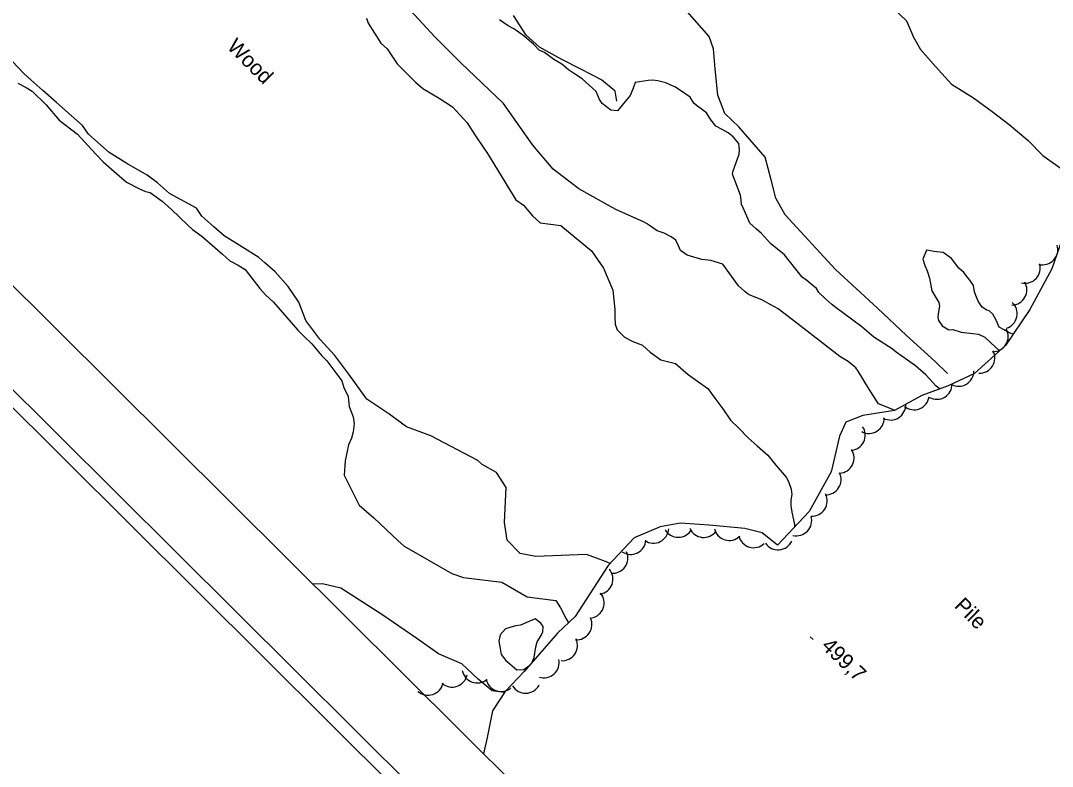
# Model space of a CAD drawing. Extents: x 642515 to 647219, y 6080136 to 6084356.
# Drawn here: x 643071.4 to 643274.3, y 6081637.9 to 6081784.5 of the extents above; entities that cross this region are included whole.
import ezdxf

# ---------------------------------------------------------------- set-up
doc = ezdxf.new("R2010")
doc.units = 0
for name, color, linetype in [('Level 1', 7, 'Continuous'), ('Level 2', 7, 'Continuous'), ('Level 3', 7, 'Continuous'), ('Level 4', 7, 'Continuous'), ('Level 44', 7, 'Continuous'), ('Level 57', 7, 'Continuous'), ('Level 60', 7, 'Continuous')]:
    doc.layers.add(name, color=color, linetype=linetype)

msp = doc.modelspace()

# ---------------------------------------------------------------- linework, layer by layer
at = {"layer": 'Level 1'}
msp.add_lwpolyline([(643187.32, 6081677.78), (643186.4, 6081678.13), (643184.6, 6081678.82), (643182.64, 6081679.51), (643172.67, 6081679.14), (643169.6, 6081679.75), (643167.04, 6081682.32), (643166.51, 6081685.81), (643166.88, 6081692.72), (643164.94, 6081695.65), (643162.12, 6081697.24), (643161.28, 6081697.99), (643152.02, 6081702.87), (643147.28, 6081704.66), (643143.77, 6081707.17), (643139.43, 6081710.11), (643135.93, 6081715.03), (643133.14, 6081718.7), (643130.23, 6081721.89), (643127.44, 6081725.57), (643126.1, 6081729.17), (643123.99, 6081732.25), (643121.42, 6081735.13), (643119.39, 6081736.93), (643118.2, 6081737.98), (643114.88, 6081740.02), (643111.39, 6081742.21), (643109.36, 6081744.01), (643106.99, 6081746.11), (643105.94, 6081747.65), (643100.64, 6081750.53), (643098.27, 6081752.63), (643096.26, 6081754.11), (643092.28, 6081756.43), (643088.79, 6081758.62), (643087.1, 6081760.12), (643084.73, 6081762.22), (643083.51, 6081763.91), (643081.31, 6081765.86), (643078.43, 6081768.41), (643075.73, 6081770.81), (643073.36, 6081772.91), (643072.01, 6081774.11), (643068.58, 6081777.74)], dxfattribs=at)
at = {"layer": 'Level 2'}
for points in [[(643243.28, 6081707.85), (643242.9, 6081708.03), (643240.1, 6081709.15), (643238.15, 6081712.24), (643236.1, 6081715.57), (643235.65, 6081716.27), (643234.14, 6081717.46), (643232.47, 6081718.49), (643224.05, 6081725.04), (643220.35, 6081727.87), (643218.94, 6081728.67), (643217.28, 6081729.53), (643214.49, 6081730.65), (643213.81, 6081731.25), (643212.54, 6081732.38), (643209.47, 6081736.61), (643207.1, 6081737.35), (643205.32, 6081737.56), (643203.77, 6081738.03), (643202.47, 6081738.43), (643201.97, 6081738.72), (643201.13, 6081739.31), (643200.75, 6081740.25), (643200.2, 6081741.35), (643199.28, 6081742.01), (643197.95, 6081742.74), (643196.56, 6081743.21), (643195.22, 6081744.1), (643194.47, 6081744.61), (643193.97, 6081744.9), (643188.45, 6081747.38), (643181.14, 6081751.43), (643176.09, 6081755.3), (643172.11, 6081760.04), (643166.32, 6081768.21), (643157.97, 6081776.22), (643152.84, 6081781.37), (643146.48, 6081788.21)], [(643139.39, 6081785.05), (643139.7, 6081784.03), (643142.2, 6081780.1), (643143.48, 6081778.98), (643145.44, 6081776.07), (643147.5, 6081773.96), (643149.04, 6081772.45), (643150.49, 6081771.18), (643153.66, 6081769.31), (643156.34, 6081767.56), (643159.19, 6081764.46), (643160.71, 6081762.07), (643162.49, 6081759.46), (643163.2, 6081758.38), (643168.77, 6081749.28), (643170.28, 6081748.26), (643172.03, 6081746.13), (643173.56, 6081744.79), (643177.6, 6081744.25), (643183.62, 6081739.28), (643186.01, 6081735.82), (643187.82, 6081731.53), (643188.24, 6081727.7), (643188.26, 6081726.18), (643188.27, 6081724.82), (643188.67, 6081723.72), (643190.13, 6081722.29), (643191.78, 6081721.44), (643193.68, 6081720.68), (643195.21, 6081719.34), (643197.31, 6081717.79), (643200.16, 6081717.1), (643202.63, 6081714.94), (643204.48, 6081713.62), (643206.5, 6081712.15)], [(643199.14, 6081771.9), (643198.27, 6081772.28), (643196.67, 6081772.7), (643195.7, 6081772.8), (643194.78, 6081772.77), (643192.24, 6081772.36), (643191.8, 6081771.09), (643191.24, 6081769.84), (643189.65, 6081767.93), (643188.76, 6081766.82), (643187.47, 6081766.9), (643185.73, 6081768.27), (643185.24, 6081769), (643184.53, 6081770.61), (643181.79, 6081773.08), (643180.53, 6081773.96), (643179.14, 6081774.88), (643177.78, 6081775.99), (643176.23, 6081776.9), (643174.37, 6081778.3), (643173.38, 6081778.72), (643172.22, 6081779.89), (643170.94, 6081781.01), (643170.17, 6081781.69), (643168.4, 6081782.94), (643167.24, 6081783.51), (643165.55, 6081784.68)], [(643070.82, 6081772.24), (643072.47, 6081771.39), (643073.64, 6081770.67), (643076.37, 6081767.97), (643078.97, 6081764.94), (643082.59, 6081762.22), (643086.12, 6081758.37), (643087.58, 6081756.79), (643089.79, 6081754.85), (643092.17, 6081752.77), (643094.65, 6081751.5), (643095.96, 6081750.94), (643096.85, 6081750.76), (643099.21, 6081749), (643101.07, 6081747.36), (643104.23, 6081744.29), (643105.16, 6081743.47), (643107.01, 6081742.16)], [(643251.34, 6081712.69), (643250.17, 6081714.03), (643249.39, 6081714.86), (643247.9, 6081716.17), (643247.34, 6081716.65), (643245.82, 6081717.76), (643243.59, 6081719.34), (643242.78, 6081719.97), (643239.14, 6081722.27), (643236.83, 6081724.29), (643233.28, 6081726.95), (643231.76, 6081728.06), (643230.83, 6081728.8), (643229.67, 6081729.81), (643228.38, 6081731.09), (643227.89, 6081731.82), (643226.87, 6081732.72), (643225.98, 6081733.43), (643225.09, 6081734.05), (643221.58, 6081738.49), (643218.82, 6081740.68), (643217.09, 6081742.66), (643216.02, 6081743.59), (643215.42, 6081744.12), (643214.78, 6081744.68), (643214.4, 6081745.62), (643213.26, 6081748.2), (643213.13, 6081748.31), (643213.1, 6081749.32), (643212.92, 6081750.23), (643211.4, 6081754.36), (643211.52, 6081755.01), (643212.7, 6081758.27), (643212.72, 6081759.15), (643212.6, 6081760.39), (643211.51, 6081761.65), (643210.49, 6081762.47), (643209.32, 6081763.11), (643208.11, 6081763.8), (643207.19, 6081764.98), (643206.66, 6081765.75), (643206.29, 6081766.37), (643205.19, 6081767.19), (643204.27, 6081767.85), (643203.75, 6081768.3), (643203.03, 6081769.46), (643201.98, 6081770.23), (643201.14, 6081770.82), (643200.01, 6081771.51), (643199.14, 6081771.9)], [(643107.01, 6081742.16), (643109.55, 6081739.92), (643111.08, 6081738.59), (643112.52, 6081737.32), (643114.18, 6081736.47), (643115.51, 6081735.6), (643118.4, 6081731.87), (643119.52, 6081730.58), (643121.13, 6081729.17), (643125.9, 6081723.65), (643127.01, 6081722.52), (643128.63, 6081720.95), (643130.63, 6081718.6), (643131.57, 6081717.62), (643132.97, 6081715.8), (643134.55, 6081713.66), (643134.95, 6081712.41), (643135.79, 6081710.62), (643136.01, 6081708.64), (643136.3, 6081707.77), (643136.78, 6081706.61), (643136.95, 6081705.26), (643136.74, 6081703.64), (643136.42, 6081702.42), (643135.87, 6081701.1), (643135.21, 6081697.94), (643135.11, 6081696.97), (643135, 6081695.12), (643137.95, 6081689.24), (643140.83, 6081686.71), (643145.61, 6081682.23), (643146.79, 6081681.18), (643156.18, 6081675.81), (643158.46, 6081675), (643166.03, 6081674.06), (643171.01, 6081671.2), (643176.65, 6081670.45), (643177.54, 6081669.07), (643178.64, 6081666.9), (643179.12, 6081666.09)], [(643266.55, 6081722.84), (643265.77, 6081723.11), (643264.77, 6081723.69), (643263.85, 6081724.27), (643263.23, 6081725.64), (643262.59, 6081726.81), (643261.87, 6081727.44), (643261.37, 6081727.57), (643260.49, 6081728.2), (643259.69, 6081729.35), (643259.21, 6081730.45), (643258.96, 6081731.19), (643258.76, 6081732.43), (643258.04, 6081733.51), (643257.52, 6081734.12), (643256.86, 6081735), (643255.88, 6081735.86), (643254.43, 6081737.74), (643253.29, 6081738.59), (643252.78, 6081738.95), (643251, 6081739.16), (643250.39, 6081739.24), (643249.54, 6081739.38), (643248.82, 6081737.6), (643249.18, 6081736.38), (643249.69, 6081735.33), (643250.11, 6081733.91), (643250.6, 6081731.36), (643251.96, 6081729.12), (643252.09, 6081728.4), (643251.79, 6081726.85), (643251.76, 6081726.13), (643251.88, 6081725.57), (643252.63, 6081724.53), (643253.93, 6081723.69), (643254.69, 6081723.79), (643256.33, 6081723.25), (643258.67, 6081723), (643259.77, 6081722.88), (643260.97, 6081722.27), (643262.21, 6081721.19), (643263.71, 6081719.8), (643263.86, 6081719.54)], [(643206.5, 6081712.15), (643207.9, 6081710.31), (643209.49, 6081708.17), (643211, 6081705.94), (643212.63, 6081704.37), (643214.43, 6081702.48), (643216.22, 6081700.91), (643218.35, 6081699.05), (643219.92, 6081697.07), (643221.92, 6081694.71), (643222.38, 6081693.86), (643222.88, 6081692.37), (643223.03, 6081691.33), (643222.86, 6081690.28), (643222.86, 6081689.08), (643223.02, 6081687.88), (643223.59, 6081685.43), (643223.58, 6081684.94)], [(643252.09, 6081712.09), (643251.34, 6081712.69)], [(643166.5, 6081652.39), (643164.13, 6081652.72), (643161.36, 6081655.02), (643158.14, 6081658.02), (643153.56, 6081659.98), (643149.31, 6081662.99), (643142.4, 6081667.76), (643134.36, 6081672.94), (643130.72, 6081673.76), (643128.88, 6081673.67)], [(643172.57, 6081666.85), (643170.71, 6081666.09), (643169.7, 6081665.62), (643168.67, 6081665.47), (643166.71, 6081664.94), (643165.68, 6081663.75), (643165.44, 6081662.46), (643165.7, 6081661.03), (643165.86, 6081659.84), (643166.81, 6081658.71), (643167.58, 6081658.04), (643168.93, 6081656.85), (643170.36, 6081656.94), (643171.35, 6081657.6)], [(643171.99, 6081658.35), (643172.36, 6081659.24), (643172.7, 6081661.34), (643172.96, 6081662.32), (643173.75, 6081663.57), (643174.1, 6081664.31), (643174.11, 6081665.35), (643173.66, 6081666.05), (643172.57, 6081666.85)]]:
    msp.add_lwpolyline(points, dxfattribs=at)
at = {"layer": 'Level 3'}
msp.add_line((643226.66, 6081663.36), (643227.23, 6081662.8), dxfattribs=at)
at = {"layer": 'Level 4'}
for points in [[(643253.68, 6081715.13), (643251.2, 6081717.48), (643245.59, 6081722.61), (643239.87, 6081727.98), (643231.61, 6081735.61), (643221.71, 6081746.36), (643219.9, 6081749.63), (643218.95, 6081753.2), (643217.79, 6081757.71), (643212.6, 6081763.68), (643209.87, 6081766.25), (643208.52, 6081769.87), (643207.96, 6081775.07), (643207.64, 6081779), (643206.76, 6081781.44), (643202.44, 6081786.34)], [(643242.94, 6081787), (643245.58, 6081784.5), (643246.99, 6081781.29), (643248.34, 6081778.87), (643251.29, 6081775.5), (643254.47, 6081772.07), (643258.74, 6081769.35), (643262.44, 6081766.68), (643265.81, 6081764.14), (643269.54, 6081760.98), (643272.38, 6081758.02), (643276.75, 6081754.9)], [(643188.6, 6081768.73), (643188.32, 6081770.64), (643185.61, 6081772.89), (643181.54, 6081774.98), (643177.81, 6081776.92), (643173.41, 6081779.31), (643170.77, 6081781.65), (643168.28, 6081785.52)]]:
    msp.add_lwpolyline(points, dxfattribs=at)
at = {"layer": 'Level 44'}
for centre, start, end in [((643272.35, 6081739.51), 256.5474, 16.5253), ((643268.91, 6081735.88), 256.5474, 16.5253), ((643266.27, 6081731.57), 271.1396, 31.1176), ((643264.37, 6081726.91), 287.6523, 47.6302), ((643262.6, 6081722.42), 268.112, 28.09), ((643259.95, 6081718.18), 268.112, 28.09), ((643255.84, 6081715.62), 241.0623, 1.0402), ((643251.56, 6081713.05), 241.0623, 1.0402), ((643242.45, 6081708.98), 241.911, 1.8889), ((643247.07, 6081710.99), 231.3571, 351.335), ((643238.2, 6081706.34), 241.911, 1.8889), ((643234.48, 6081703), 273.862, 33.8399), ((643232.28, 6081698.51), 273.862, 33.8399), ((643229.74, 6081694.26), 266.8646, 26.8425), ((643227, 6081690.08), 266.8646, 26.8425), ((643223.96, 6081686.21), 256.0057, 15.9837), ((643205.73, 6081685.88), 203.3669, 323.3449), ((643195.83, 6081684.76), 236.4549, 356.4328), ((643200.7, 6081685.92), 210.2658, 330.2438), ((643210.75, 6081685.29), 193.5087, 313.4866), ((643215.54, 6081683.87), 193.5087, 313.4866), ((643191.35, 6081682.54), 236.4549, 356.4328), ((643220.33, 6081683.44), 214.673, 334.6509), ((643187.81, 6081678.84), 264.2282, 24.2062), ((643184.87, 6081674.7), 279.7184, 39.6964), ((643183.13, 6081670.01), 279.7184, 39.6964), ((643180.73, 6081665.76), 265.4102, 25.3881), ((643177.89, 6081661.64), 265.4102, 25.3881), ((643174.3, 6081658.27), 252.2405, 12.2184), ((643161.17, 6081657.26), 190.2485, 310.2265), ((643151.5, 6081654.86), 228.5494, 348.5273), ((643156.24, 6081656.45), 228.5494, 348.5273), ((643165.87, 6081655.57), 190.2485, 310.2265), ((643170.69, 6081655.24), 211.2697, 331.2477)]:
    msp.add_arc(centre, 3, start, end, dxfattribs=at)
at = {"layer": 'Level 57'}
msp.add_lwpolyline([(643276.78, 6081743.26), (643274.19, 6081735.71), (643269.85, 6081727.74), (643265.06, 6081720.63), (643258.97, 6081715.12), (643253.81, 6081712.73), (643248.62, 6081710.81), (643243.26, 6081707.84), (643236.98, 6081706.9), (643233.69, 6081705.58), (643232.42, 6081702.78), (643230.76, 6081695.78), (643226.42, 6081687.99), (643220.25, 6081681.38), (643217.22, 6081683.76), (643213.8, 6081684.67), (643206.8, 6081685.29), (643201.09, 6081685.67), (643197.13, 6081684.95), (643192.05, 6081682.8), (643186.94, 6081677.38), (643180.44, 6081667.32), (643176.96, 6081664.08), (643170.39, 6081656.5), (643166.64, 6081652.61), (643164.16, 6081648.79), (643163.12, 6081643.55), (643162.41, 6081640.34)], dxfattribs=at)
at = {"layer": 'Level 60'}
for points in [[(643756.15, 6083509.1), (645893.11, 6081385.05), (644652.25, 6080135.58), (642514.75, 6082260.08)], [(642518.29, 6082260.09), (643756.16, 6083505.56), (645889.57, 6081385.04), (644651.74, 6080139.63)], [(643756.23, 6083485.06), (645517.55, 6081734.46), (644300.6, 6080509.08), (642538.79, 6082260.16)]]:
    msp.add_lwpolyline(points, close=True, dxfattribs=at)

# ---------------------------------------------------------------- texts
at = {"layer": 'Level 3'}
msp.add_text('499,7', height=3, rotation=315.59, dxfattribs=at).set_placement((643228.69, 6081661.32))
at = {"layer": 'Level 44'}
msp.add_text('Wood', height=3, rotation=315.1749, dxfattribs=at).set_placement((643111.78, 6081779.2))
at = {"layer": 'Level 57'}
msp.add_text('Pile', height=3, rotation=315.1749, dxfattribs=at).set_placement((643254.82, 6081669.26))

doc.saveas('drawing.dxf')
